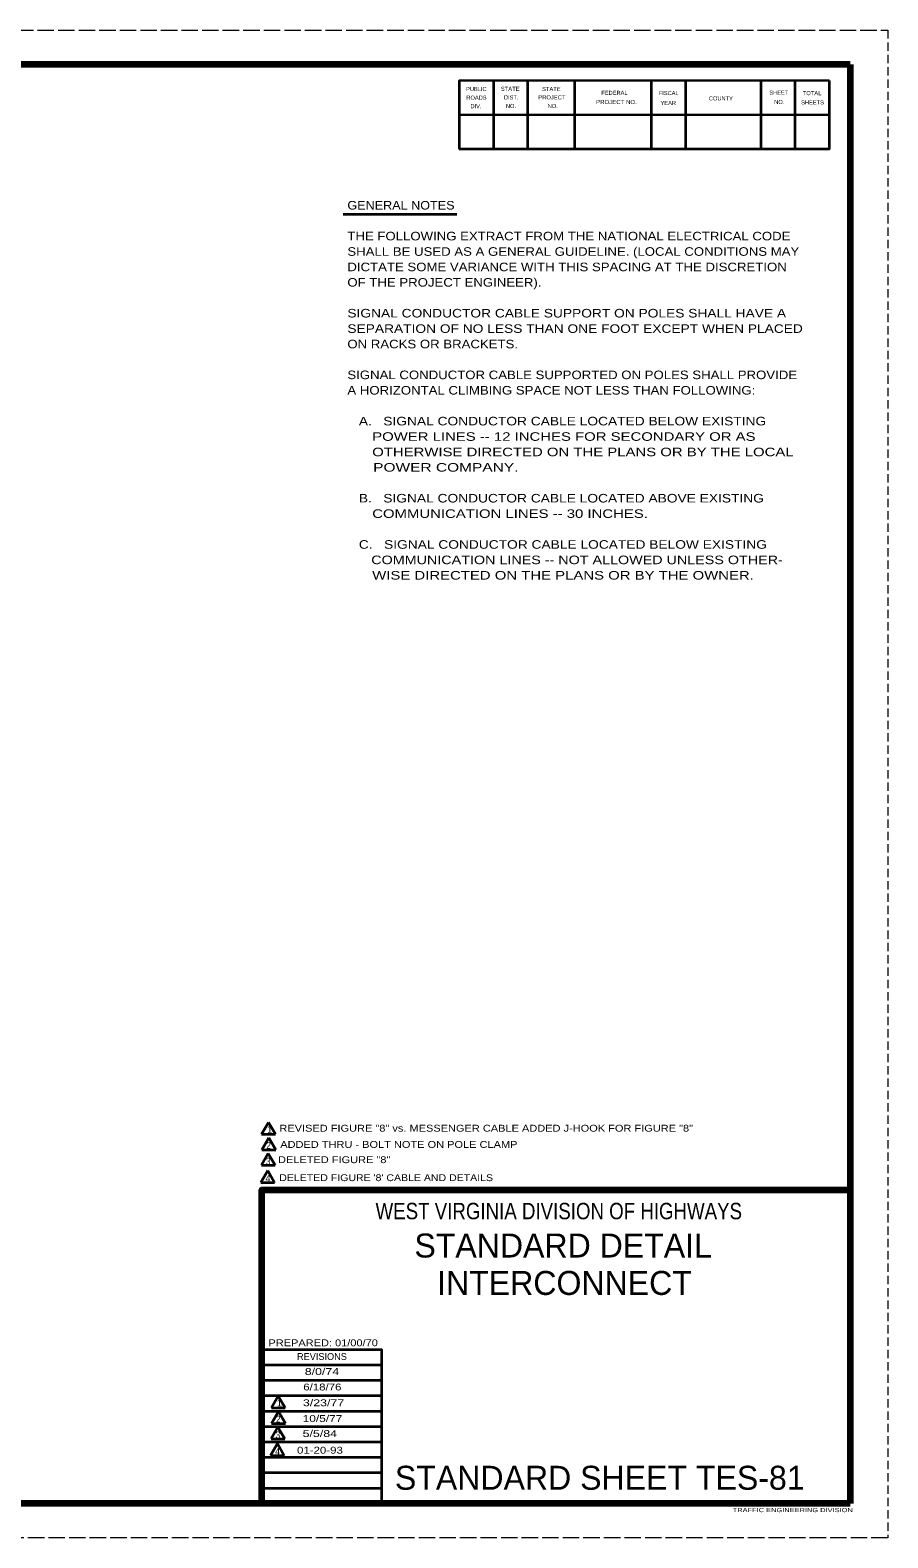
# Model space of a CAD drawing. Extents: x -368 to 312, y -34 to 406.
# Drawn here: x 62 to 312.1, y -34 to 406 of the extents above; entities that cross this region are included whole.
import ezdxf
from ezdxf.enums import TextEntityAlignment as Align

# ---------------------------------------------------------------- set-up
doc = ezdxf.new("R2010")
doc.units = 0
doc.header["$LTSCALE"] = 0.8
doc.linetypes.add('LONG_DASHED', pattern=[7.5, 6, -1.5])
doc.linetypes.add('MEDIUM_DASHED', pattern=[4.5, 3, -1.5])
doc.layers.add('1', color=7, linetype='Continuous', lineweight=53)
doc.layers.add('61', color=7, linetype='Continuous', lineweight=35)

msp = doc.modelspace()

# ---------------------------------------------------------------- linework, layer by layer
at = {"layer": '1', "linetype": 'MEDIUM_DASHED', "lineweight": 13}
msp.add_line((312.1185, 406.0392), (312.0985, -33.9808), dxfattribs=at)
at = {"layer": '1', "lineweight": 35}
for p, q in [((153.2658, 352.3352), (186.4113, 352.3352)), ((131.4716, 87.2437), (129.4716, 83.7797)), ((129.4716, 83.7797), (133.4716, 83.7797)), ((131.4716, 87.2437), (133.4716, 83.7797)), ((131.5601, 82.7297), (129.5601, 79.2656)), ((129.5601, 79.2656), (133.5601, 79.2656)), ((131.5601, 82.7297), (133.5601, 79.2656)), ((131.3832, 78.2154), (129.3832, 74.7513)), ((131.3832, 78.2154), (133.3832, 74.7513)), ((131.2638, 73.2017), (129.2638, 69.7376)), ((129.3832, 74.7513), (133.3832, 74.7513)), ((131.2638, 73.2017), (133.2638, 69.7376)), ((129.2638, 69.7376), (133.2638, 69.7376)), ((164.4985, 16.4392), (129.5185, 16.4392)), ((164.4985, 11.9392), (129.5185, 11.9392)), ((164.4985, 7.4392), (129.5185, 7.4392)), ((134.2983, 7.3635), (132.2983, 3.8994)), ((134.2983, 7.3635), (136.2983, 3.8994)), ((164.4985, 2.9192), (129.5185, 2.9192)), ((132.2983, 3.8994), (136.2983, 3.8994)), ((134.3868, 2.8494), (132.3868, -0.6147)), ((134.3868, 2.8494), (136.3868, -0.6147)), ((164.4985, -1.5607), (129.5185, -1.5607)), ((134.2099, -1.6648), (132.2099, -5.1289)), ((132.3868, -0.6147), (136.3868, -0.6147)), ((134.2099, -1.6648), (136.2099, -5.1289)), ((164.4985, -6.0408), (129.5185, -6.0408)), ((134.0563, -6.4869), (132.0563, -9.951)), ((132.2099, -5.1289), (136.2099, -5.1289)), ((134.0563, -6.4869), (136.0563, -9.951)), ((164.4985, -10.5407), (129.5185, -10.5407)), ((132.0563, -9.951), (136.0563, -9.951)), ((164.4985, -15.0407), (129.5185, -15.0407)), ((164.4985, -19.5607), (129.5185, -19.5607))]:
    msp.add_line(p, q, dxfattribs=at)
at = {"layer": '1', "lineweight": 158}
msp.add_lwpolyline([(129.4985, -24.0008), (129.4985, 67.5793), (301.1585, 67.5793)], dxfattribs=at)
at = {"layer": '1', "lineweight": 35}
msp.add_lwpolyline([(164.4985, -24.0407), (164.4985, 20.9192), (129.5185, 20.9192)], dxfattribs=at)
at = {"layer": '61', "linetype": 'LONG_DASHED', "lineweight": 13}
for p, q in [((-367.9015, 406.0392), (312.1185, 406.0392)), ((312.0985, -33.9808), (-367.9615, -34.0007))]:
    msp.add_line(p, q, dxfattribs=at)
at = {"layer": '61', "lineweight": 158}
for p, q in [((301.1385, 396.0392), (301.1585, -24.0008)), ((301.1585, -24.0008), (-337.9015, -23.9808))]:
    msp.add_line(p, q, dxfattribs=at)
at = {"layer": '61'}
for p, q in [((197.0585, 391.2792), (197.0585, 371.2792)), ((207.0585, 391.2792), (207.0585, 371.2792)), ((220.7385, 391.2792), (220.7385, 371.2792)), ((243.0585, 391.2792), (243.0585, 371.2792)), ((253.0585, 391.2792), (253.0585, 371.2792)), ((275.0385, 391.2992), (275.0385, 371.2992)), ((285.0385, 391.2992), (285.0385, 371.2992)), ((295.0585, 381.2593), (187.0385, 381.2792))]:
    msp.add_line(p, q, dxfattribs=at)
at = {"layer": '61', "lineweight": 158}
msp.add_lwpolyline([(301.1385, 396.0392), (-337.9015, 396.0392), (-337.9015, -23.9808)], dxfattribs=at)
at = {"layer": '61'}
for points in [[(295.0385, 391.2992), (187.0585, 391.2792), (187.0585, 371.2792)], [(295.0385, 391.2992), (295.0385, 371.2992), (187.0585, 371.2792)]]:
    msp.add_lwpolyline(points, dxfattribs=at)

# ---------------------------------------------------------------- texts
at = {"layer": '1'}
for s, height, width, p in [('GENERAL NOTES', 2.5, 1.1, (154.4759, 353.6805)), ('THE FOLLOWING EXTRACT FROM THE NATIONAL ELECTRICAL CODE', 2.5, 1.15, (154.4759, 344.6805)), ('SHALL BE USED AS A GENERAL GUIDELINE. (LOCAL CONDITIONS MAY', 2.5, 1.15, (154.4759, 340.1805)), ('DICTATE SOME VARIANCE WITH THIS SPACING AT THE DISCRETION', 2.5, 1.15, (154.4759, 335.6805)), ('OF THE PROJECT ENGINEER).', 2.5, 1.15, (154.4759, 331.1805)), ('SIGNAL CONDUCTOR CABLE SUPPORT ON POLES SHALL HAVE A', 2.5, 1.2, (154.4759, 322.1805)), ('SEPARATION OF NO LESS THAN ONE FOOT EXCEPT WHEN PLACED', 2.5, 1.2, (154.4759, 317.6805)), ('ON RACKS OR BRACKETS.', 2.5, 1.15, (154.4759, 313.1805)), ('SIGNAL CONDUCTOR CABLE SUPPORTED ON POLES SHALL PROVIDE', 2.5, 1.15, (154.4759, 304.1805)), ('A HORIZONTAL CLIMBING SPACE NOT LESS THAN FOLLOWING:', 2.5, 1.15, (154.4759, 299.6805)), ('   A.   SIGNAL CONDUCTOR CABLE LOCATED BELOW EXISTING', 2.5, 1.2, (154.4759, 290.6805)), ('      POWER LINES -- 12 INCHES FOR SECONDARY OR AS', 2.5, 1.3, (154.4759, 286.1805)), ('      OTHERWISE DIRECTED ON THE PLANS OR BY THE LOCAL', 2.5, 1.3, (154.4759, 281.6805)), ('      POWER COMPANY.', 2.5, 1.35, (154.4759, 277.1805)), ('   B.   SIGNAL CONDUCTOR CABLE LOCATED ABOVE EXISTING', 2.5, 1.2, (154.4759, 268.1805)), ('      COMMUNICATION LINES -- 30 INCHES.', 2.5, 1.3, (154.4759, 263.6805)), ('   C.   SIGNAL CONDUCTOR CABLE LOCATED BELOW EXISTING', 2.5, 1.2, (154.4759, 254.6805)), ('      COMMUNICATION LINES -- NOT ALLOWED UNLESS OTHER-', 2.5, 1.25, (154.4759, 250.1805)), ('      WISE DIRECTED ON THE PLANS OR BY THE OWNER.', 2.5, 1.3, (154.4759, 245.6805)), ('2', 1.998, 0.9, (130.813, 79.5241)), ('3', 1.998, 0.9, (130.7246, 74.9215)), ('4', 1.998, 0.95, (130.6052, 69.9077)), ('PREPARED: 01/00/70', 1.998, 1.2, (131.4585, 21.9192)), ('8/0/74', 1.998, 1.35, (142.0457, 13.5403)), ('6/18/76', 1.998, 1.25, (141.6033, 9.0261)), ('3/23/77', 1.998, 1.35, (141.5148, 4.4236)), ('2', 1.998, 0.9, (133.6397, -0.3562)), ('10/5/77', 1.998, 1.3, (141.4263, -0.1792)), ('3', 1.998, 0.9, (133.5513, -4.9588)), ('5/5/84', 1.998, 1.35, (141.4263, -4.5736)), ('4', 1.998, 0.95, (133.3977, -9.7808)), ('TRAFFIC ENGINEERING DIVISION', 1.2, 1.35, (266.8785, -26.5008))]:
    msp.add_text(s, height=height, dxfattribs=dict(at, width=width)).set_placement(p)
for s, height, p in [('1', 1.998, (131.0785, 84.2152)), ('REVISIONS', 1.998, (139.7785, 17.9192)), ('1', 1.998, (133.9052, 4.335)), ('STANDARD SHEET TES-81', 6.993, (168.3385, -19.9608))]:
    msp.add_text(s, height=height, dxfattribs=at).set_placement(p)
for s, height, width, p in [('REVISED FIGURE "8" vs. MESSENGER CABLE ADDED J-HOOK FOR FIGURE "8"', 2, 1.2, (194.9691, 84.5556)), ('ADDED THRU - BOLT NOTE ON POLE CLAMP', 2, 1.2, (169.4879, 79.8133)), ('DELETED FIGURE "8"', 2, 1.2, (150.624, 75.3675)), ("DELETED FIGURE '8' CABLE AND DETAILS", 2, 1.15, (165.78, 70.115)), ('WEST VIRGINIA DIVISION OF HIGHWAYS', 4.795, 0.85, (216.1468, 58.9793)), ('01-20-93', 2, 1.25, (146.4678, -9.4207))]:
    msp.add_text(s, height=height, dxfattribs=dict(at, width=width)).set_placement(p, align=Align.CENTER)
for s, p in [('STANDARD DETAIL', (217.4155, 47.8192)), ('INTERCONNECT', (217.8073, 36.9005))]:
    msp.add_text(s, height=6.993, dxfattribs=at).set_placement(p, align=Align.CENTER)
at = {"layer": '61'}
for s, rotation, p in [('PUBLIC', 0.033, (189.0985, 388.2593)), ('FEDERAL', 0.007, (228.5585, 387.1393)), ('FISCAL', 359.942, (245.2985, 387.0793)), ('SHEET', 0.059, (277.5585, 387.1993)), ('ROADS', 0.124, (189.1785, 385.7392)), ('DIV.', 359.932, (190.3785, 383.2392)), ('DIST.', 0.056, (200.1385, 385.8193)), ('YEAR', 0.105, (245.8185, 384.1792)), ('COUNTY', 0.069, (259.9185, 385.5392)), ('SHEETS', 359.959, (286.8385, 384.3592))]:
    msp.add_text(s, height=1.201, rotation=rotation, dxfattribs=at).set_placement(p)
for s, rotation, width, p in [('STATE', 0.059, 1.05, (199.2585, 388.3193)), ('STATE', 0.059, 1.05, (211.2585, 388.2593)), ('TOTAL', 359.926, 1.05, (287.2985, 387.0592)), ('NO.', 359.852, 0.95, (200.7185, 383.2992)), ('PROJECT', 359.908, 1.05, (210.1785, 385.8392)), ('NO.', 0.225, 0.95, (212.9185, 383.2992)), ('PROJECT NO.', 359.922, 1.1, (227.0185, 384.4792)), ('NO.', 359.852, 0.95, (278.9785, 384.4792))]:
    msp.add_text(s, height=1.201, rotation=rotation, dxfattribs=dict(at, width=width)).set_placement(p)

doc.saveas('drawing.dxf')
